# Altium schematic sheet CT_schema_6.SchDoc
size 308 x 301 mm
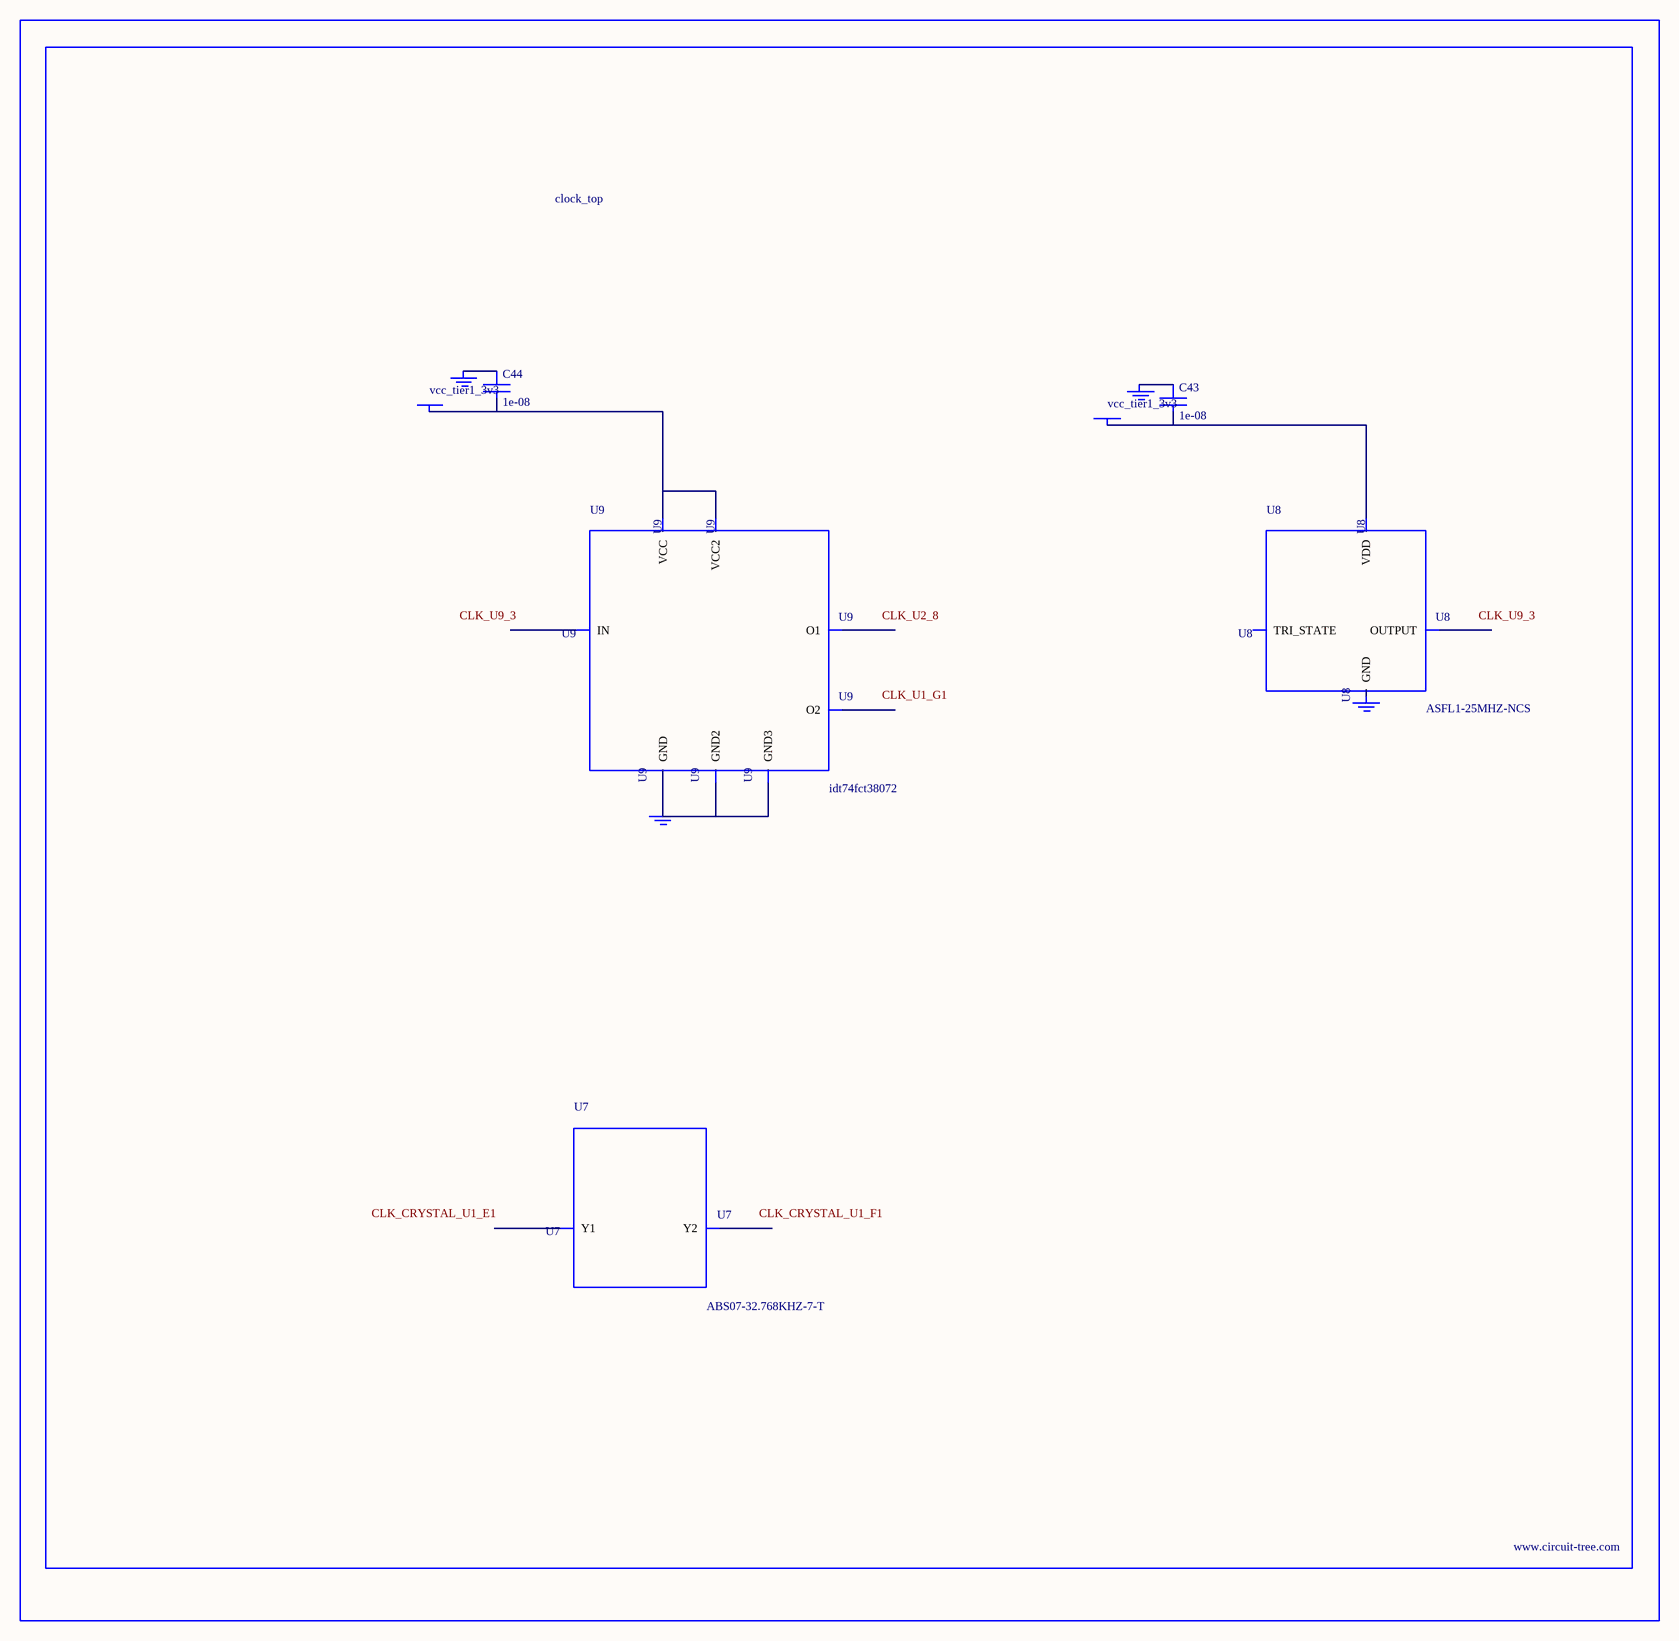
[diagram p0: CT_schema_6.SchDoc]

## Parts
BORDER5  (no value)
C43  1e-08  [C0402]
C44  1e-08  [C0402]
GND_INSTANCE_5_0  (no value)
GND_INSTANCE_5_1  (no value)
GND_INSTANCE_5_2  (no value)
GND_INSTANCE_5_3  (no value)
POWER_INSTANCE_5_0  vcc_tier1_3v3
POWER_INSTANCE_5_1  vcc_tier1_3v3
U7  ABS07-32.768KHZ-7-T  [ABS07-32.768KHZ-7-T]
U8  ASFL1-25MHZ-NCS  [ASFL1]
U9  idt74fct38072  [IDT74FCT38072]

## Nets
NetC43_1: C43.1 GND_INSTANCE_5_0.0(GND)
NetC43_2: C43.2 POWER_INSTANCE_5_0.0(PWR) U8.4(VDD)
NetC44_1: C44.1 GND_INSTANCE_5_2.0(GND)
NetC44_2: C44.2 POWER_INSTANCE_5_1.0(PWR) U9.1(VCC) U9.2(VCC2)
NetGND_INSTANCE_5_3_0: GND_INSTANCE_5_3.0(GND) U9.4(GND) U9.5(GND2) U9.8(GND3)

Not connected (* = marked no-connect by the designer): GND_INSTANCE_5_1 0(GND); U7 1(Y1) 2(Y2); U8 1(TRI_STATE) 2(GND) 3(OUTPUT); U9 3(IN) 6(O2) 7(O1)

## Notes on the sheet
- Labels drawn without touching a wire or pin: CLK_CRYSTAL_U1_E1, CLK_CRYSTAL_U1_F1, CLK_U1_G1, CLK_U2_8, CLK_U9_3

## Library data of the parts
BORDER5 = BORDER_PAGE5
C43 C44 = C0402C103K3RAC
GND_INSTANCE_5_0-GND_INSTANCE_5_3 = GND
POWER_INSTANCE_5_0 POWER_INSTANCE_5_1 = PWR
